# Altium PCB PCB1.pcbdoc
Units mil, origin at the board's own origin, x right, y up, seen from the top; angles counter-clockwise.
Board outline 2240 x 2165 mil, 2 copper layers (Top Layer, Bottom Layer); 16 components, 27 nets, 73 pads, 23 vias.
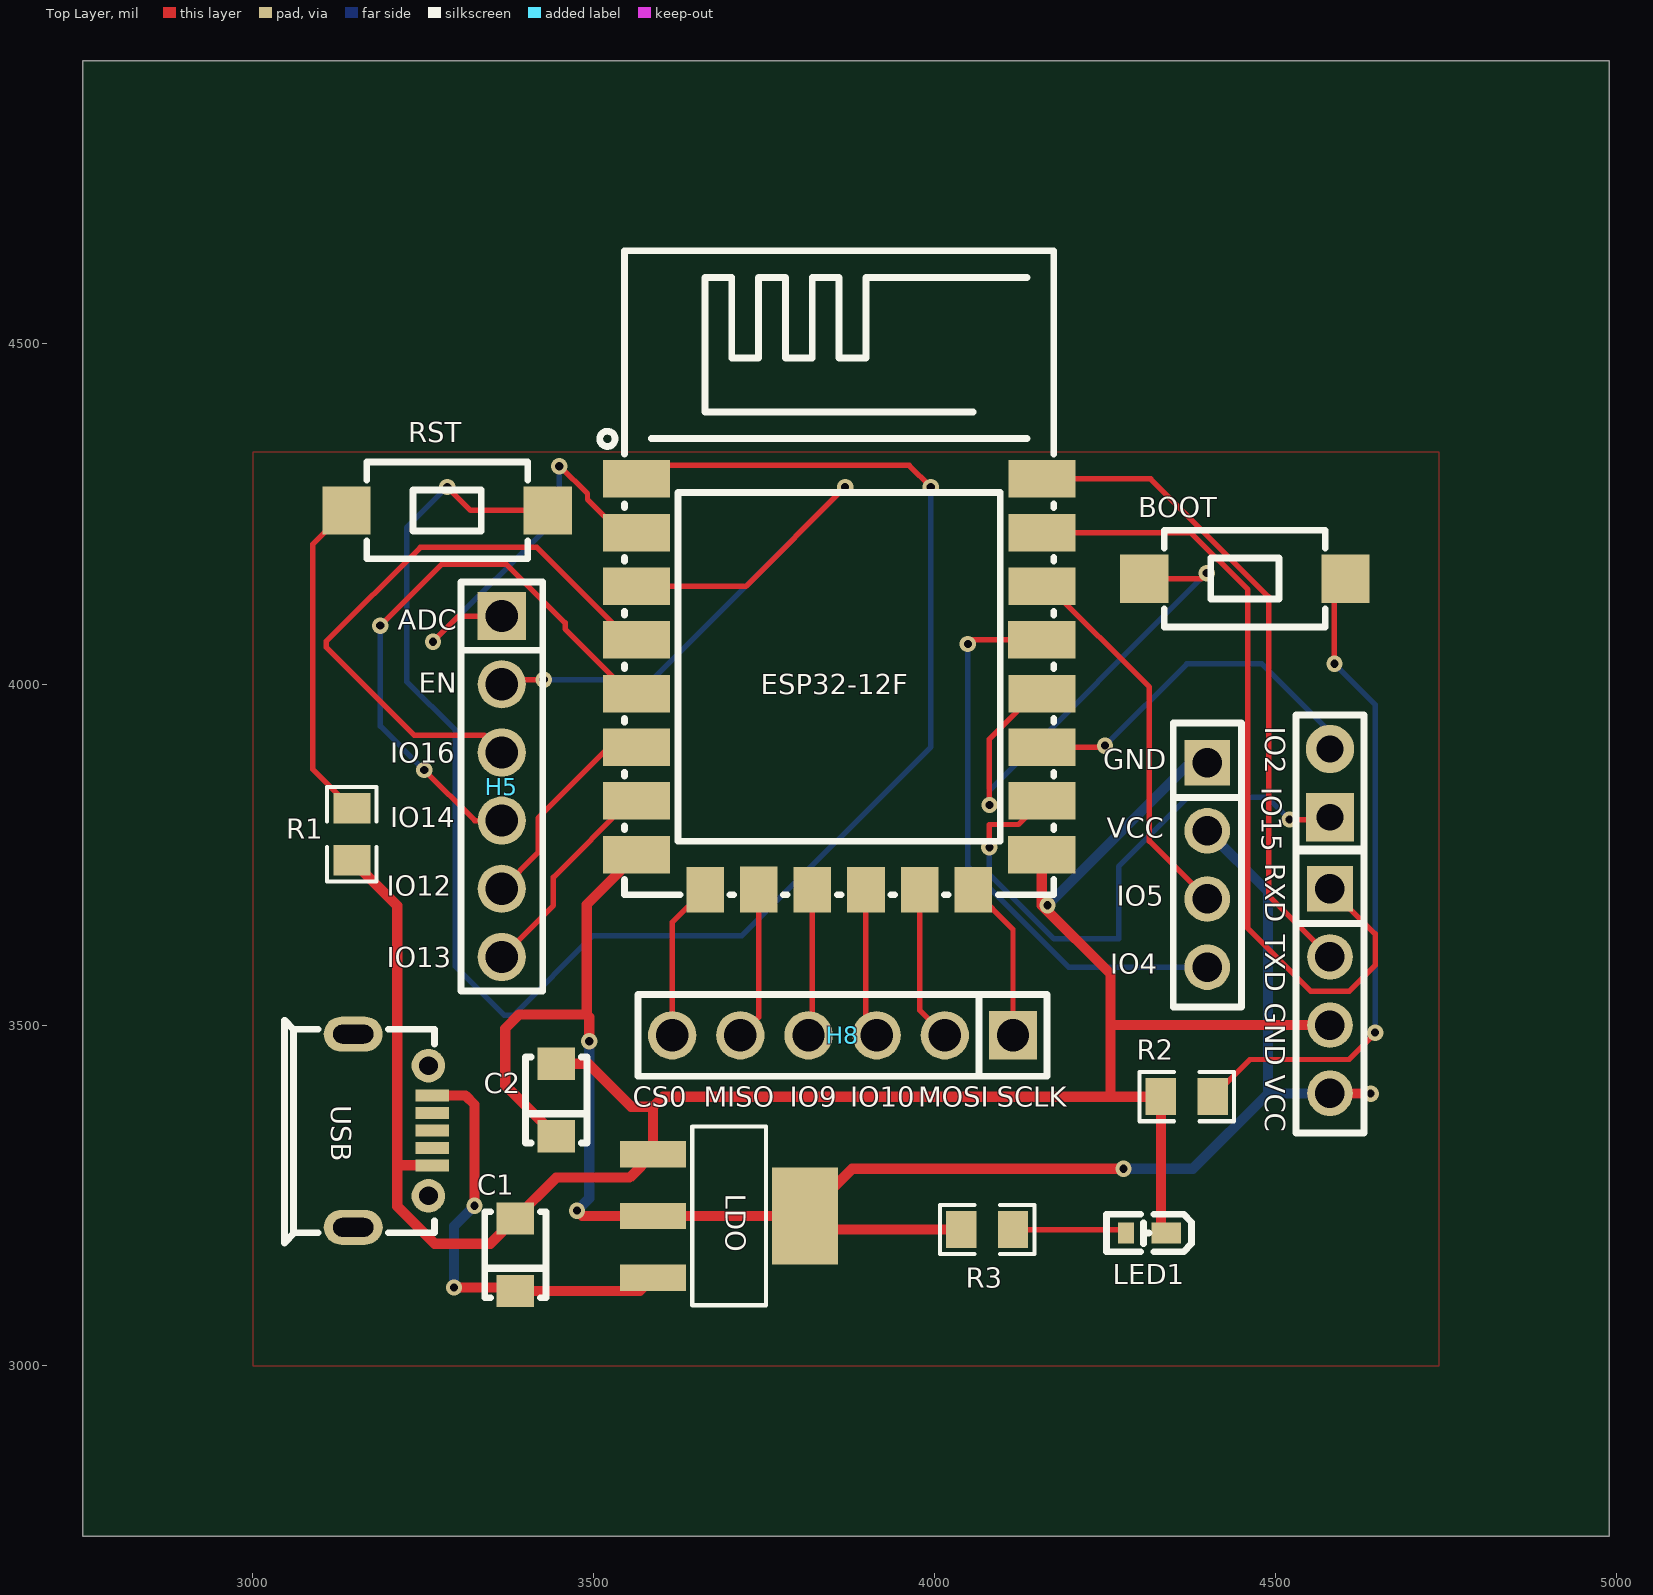
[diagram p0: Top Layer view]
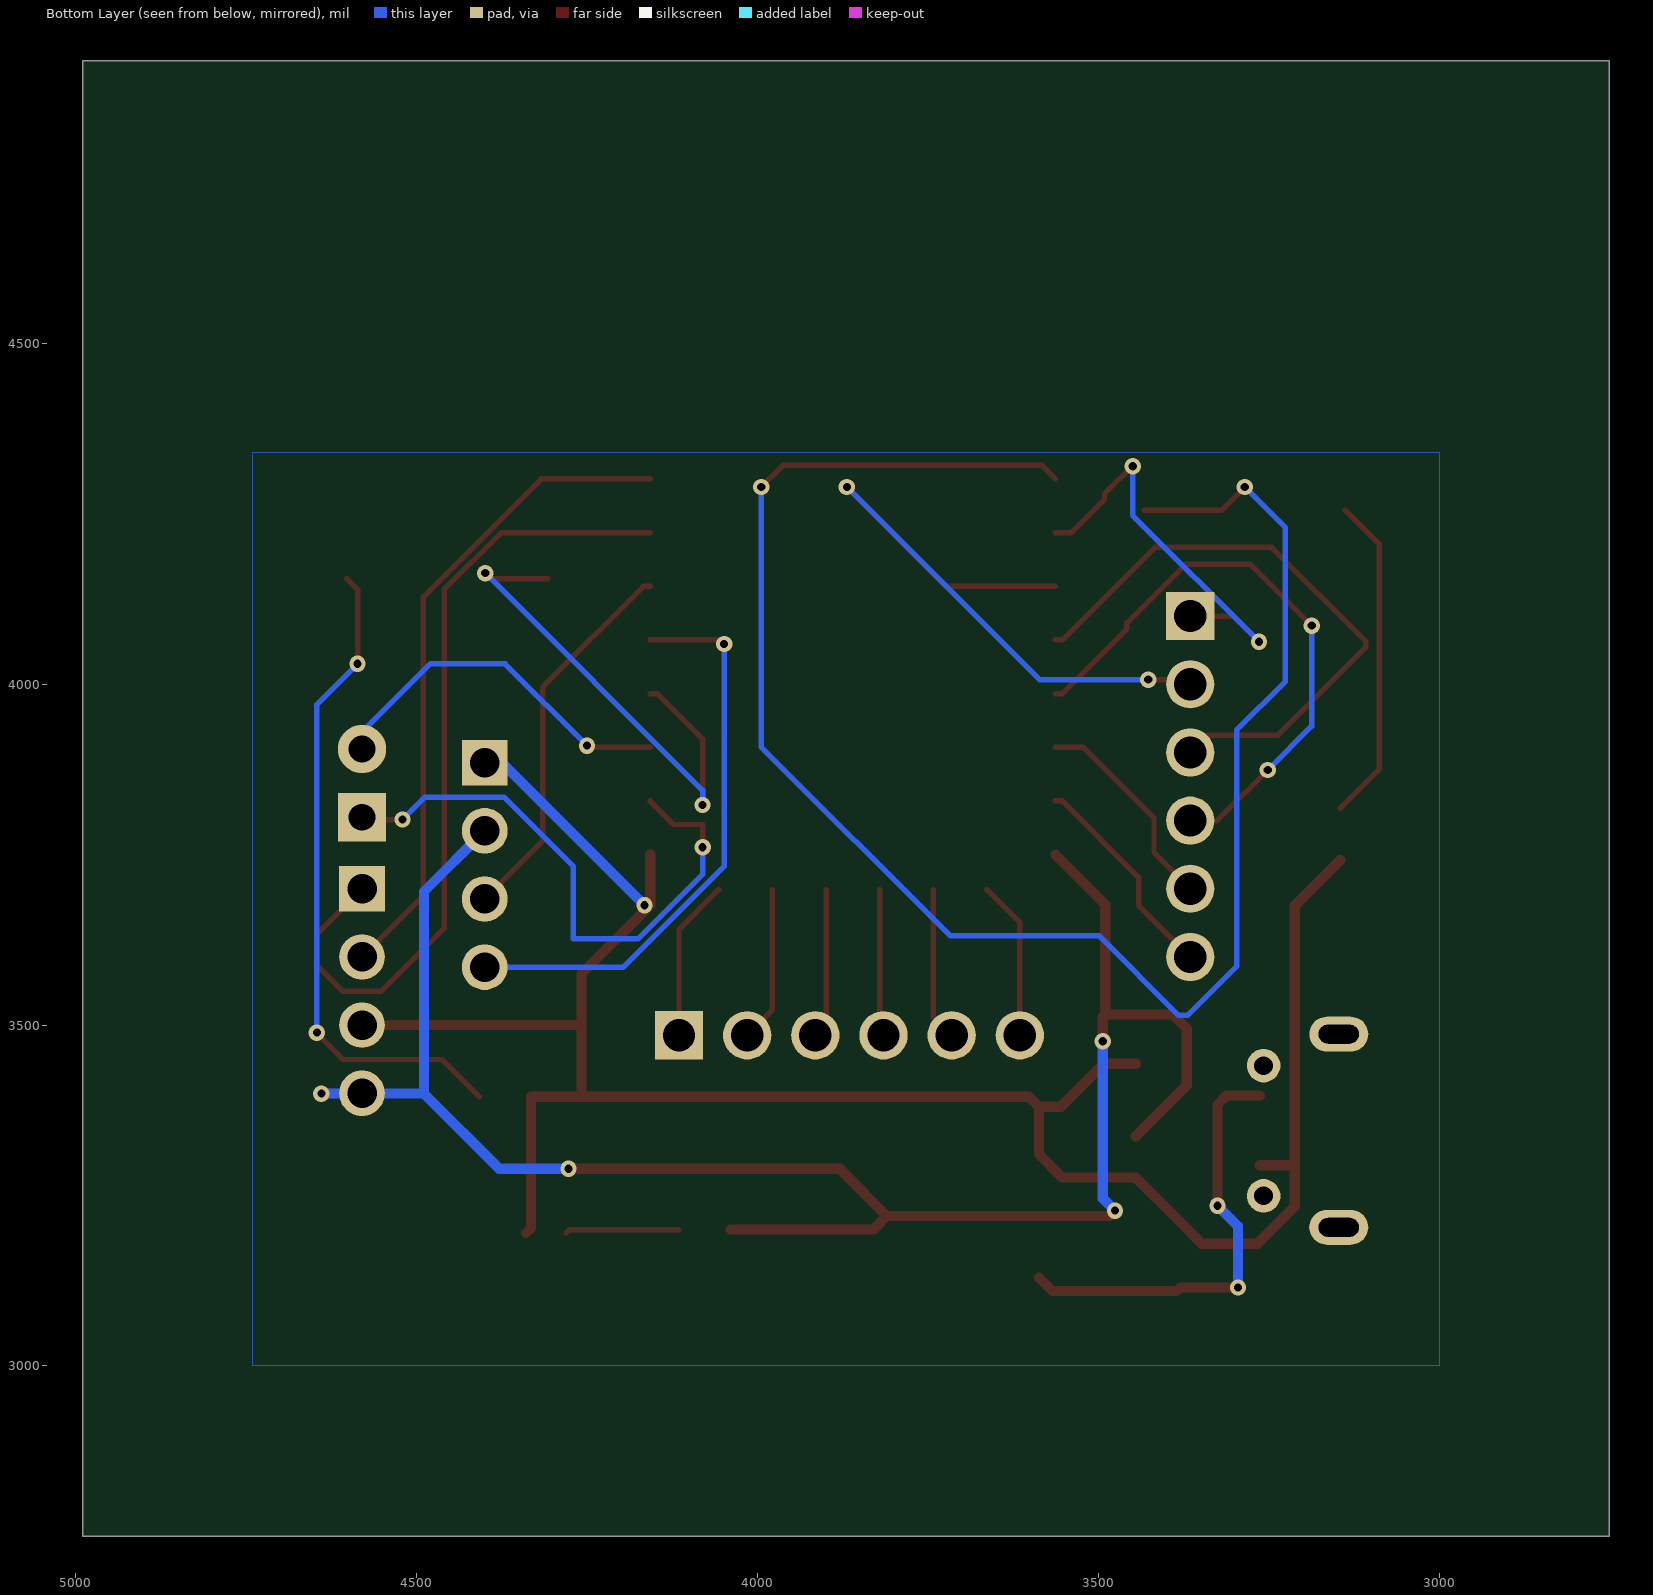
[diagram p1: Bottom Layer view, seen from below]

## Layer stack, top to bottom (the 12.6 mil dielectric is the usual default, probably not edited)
Top Solder: solder mask 0.4, Solder Resist, Dk 3.5
Top Layer: signal copper 1.4
Dielectric 1: dielectric 12.6, FR-4, Dk 4.8
Bottom Layer: signal copper 1.4
Bottom Solder: solder mask 0.4, Solder Resist, Dk 3.5

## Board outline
4990,2750 2750,2750 2750,4915 4990,4915

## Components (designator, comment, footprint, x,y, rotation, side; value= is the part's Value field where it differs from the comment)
BOOT "TC-3602-4.3-260G" 292f29fadf1e48b7a3b4ebaa9ab8793d 4455,4155 r0 top
C1 "CA45-A-16V-22uF-K" cef38e23011846a78147c20d2fc68810 3385,3163.1 r90 top
C2 "CA45-A-16V-22uF-K" cef38e23011846a78147c20d2fc68810 3445,3390 r90 top
ESP32-12F "ESP-12F(ESP8266MOD)" 6cb623ee6e8a4130b9d8b69253f68ddd 3860,4000 r270 top
H5 "Z-211-0611-0021-001" 89763fb670774c40826e2f4c92c8dd55 3365,3850 r270 top
H8 "Z-211-0611-0021-001" 89763fb670774c40826e2f4c92c8dd55 3865,3485 r180 top
IO2 "B-2100S02P-A110" aca87a76b5964f00b5eec5a18ff8502a 4580,3855 r90 top
IO15 "B-2100S04P-A110" c08b39ca13c142208e0ab31493f07b48 4400,3735 r270 top
LDO "AMS1117-2.5" 89b6391cbf9345aca1f6cf9b3f709359 3698.39,3220 r180 top
LED1 "19-213/GHC-ZN2Q1B8X/3T" LED-SMD_L1.6-W0.8-RD-2 4310,3195 r180 top
R1 "AR05DTCW1002" 005aad4e5a6043c4a1a7746d5863ed57 3145,3780 r90 top
R2 "AR05DTCW1002" 005aad4e5a6043c4a1a7746d5863ed57 4370,3395 r0 top
R3 "AR05DTCW1002" R0805 4076.96,3200 r180 top
RST "TC-3602-4.3-260G" 292f29fadf1e48b7a3b4ebaa9ab8793d 3285,4255 r180 top
RXD "B-2100S04P-A110" c08b39ca13c142208e0ab31493f07b48 4580,3550 r270 top
USB "U-F-M5DD-Y-L" c2fd68432a4d4a039f2cb9165cb8b9e0 3205,3345 r270 top

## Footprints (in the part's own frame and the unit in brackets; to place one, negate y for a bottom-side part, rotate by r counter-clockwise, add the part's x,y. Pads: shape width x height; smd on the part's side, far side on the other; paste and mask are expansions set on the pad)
005aad4e5a6043c4a1a7746d5863ed57 [mil]
  rect 44.59x54.21 smd: 1(-38.04,0) 2(38.04,0)
  silkscreen extent -69,-36 69,36
6cb623ee6e8a4130b9d8b69253f68ddd [mil]
  rect 55.1x98.4 smd: 1(-301.2,-297.3) 2(-222.5,-297.3) 3(-143.7,-297.3) 4(-65,-297.3) 5(13.8,-297.3) 6(92.5,-297.3) 7(171.2,-297.3) 8(250,-297.3) 9(250,297.2) 10(171.2,297.3) 11(92.5,297.3) 12(13.8,297.3) 13(-65,297.2) 14(-143.7,297.3) 15(-222.5,297.3) 16(-301.2,297.3)
  rect 66.9x55.1 smd: 17(301.2,-196.8) 18(301.1,-118.2) 19(301.2,-39.5) 20(301.2,39.3) 21(301.2,118) 22(301.2,196.7)
  silkscreen extent -636,-351 309,315
89b6391cbf9345aca1f6cf9b3f709359 [mm]
  rect 2.47x0.98 smd: 1(2.835,-2.3) 2(2.835,0) 3(2.835,2.3)
  rect 2.47x3.6 smd: 4(-2.835,0)
  silkscreen extent -1.37,-3.33 1.37,3.33
292f29fadf1e48b7a3b4ebaa9ab8793d [mm]
  rect 1.8x1.8 smd: 1(-3.75,0) 2(3.75,0)
  silkscreen extent -3,-1.8 3,1.8
89763fb670774c40826e2f4c92c8dd55 [mm]
  rect 1.8x1.8 hole 1.2: 1(-6.35,0)
  round 1.8 hole 1.2: 2(-3.81,0) 3(-1.27,0) 4(1.27,0) 5(3.81,0) 6(6.35,0)
  silkscreen extent -7.62,-1.52 7.62,1.52
aca87a76b5964f00b5eec5a18ff8502a [mm]
  rect 1.8x1.8 hole 1: 1(-1.27,0)
  round 1.8 hole 1: 2(1.27,0)
  silkscreen extent -2.54,-1.27 2.54,1.27
c2fd68432a4d4a039f2cb9165cb8b9e0 [mm]
  oval 1.3x2.2 hole 0.7 slot 1.5 at 90 deg: 0(-3.6,-1.471) 0(3.6,-1.47)
  round 1.25 hole 0.7: 0(-2.425,1.329) 0(2.425,1.329)
  rect 0.45x1.25 smd: 1(-1.31,1.471) 2(-0.66,1.471) 3(-0.01,1.471) 4(0.64,1.471) 5(1.29,1.471)
  silkscreen extent -4.12,-4.03 4.18,1.56
c08b39ca13c142208e0ab31493f07b48 [mil]
  rect 66.9x66.9 hole 43.3: 1(-150,0)
  round 66.9 hole 43.3: 2(-50,0) 3(50,0) 4(150,0)
  silkscreen extent -208,-50 208,50
cef38e23011846a78147c20d2fc68810 [mil]
  rect 47.2x55.1 smd: 1(-53.1,0) 2(53.2,0)
  silkscreen extent -63,-45 63,45
LED-SMD_L1.6-W0.8-RD-2 [mm]
  rect 0.6x0.8 smd: 1(0.75,0)
  rect 1.1x0.8 smd: 2(-0.75,0)
  silkscreen extent -1.7,-0.7 1.47,0.7
R0805 [mil]
  rect 44.59x54.21 smd: 1(-38.04,0) 2(38.04,0)
  silkscreen extent -69,-36 69,36

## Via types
v1: diameter 24.02, hole 12.01, Top Layer to Bottom Layer, 23 vias

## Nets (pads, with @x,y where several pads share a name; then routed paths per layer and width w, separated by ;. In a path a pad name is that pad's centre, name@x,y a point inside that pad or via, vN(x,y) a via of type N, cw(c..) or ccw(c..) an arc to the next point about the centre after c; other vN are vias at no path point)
$1N2156: BOOT.2 | length 975.3
  Top Layer w8: 4408.04,3395 4462.55,3449.51 4608.17,3449.51 4646.2,3487.55 v1(4646.2,3489) ; v1(4586.54,4030) 4586.54,4138.9 BOOT.2
  Bottom Layer w8: v1(4586.54,4030) 4646.2,3970.34 v1(4646.2,3489)
$1N2895: RST.2 | length 481.4
  Top Layer w8: RST.2 3087.55,4205.19 3087.55,3875.49 3145,3818.04
$1N6353: LED1.1 R3.1 | length 167.5
  Top Layer w8: R3.1 4275.47,3200 LED1.1
+5V: LDO.3 USB.1 | length 650.4
  Top Layer w15: USB.1 3311.99,3396.59 3325,3383.58 v1(3325,3235) ; v1(3295,3115) 3380,3115 3385,3110 3567.33,3110 LDO.3
  Bottom Layer w15: v1(3295,3115) 3295,3205 v1(3325,3235)
ADC: ESP32-12F.2 | length 609.1
  Top Layer w8: v1(3264.21,4062.44) 3301.76,4100 3365,4100 ; v1(3449.35,4319.82) 3450.69,4319.82 3490.79,4279.72 3490.79,4271.16 3539.44,4222.5 ESP32-12F.2
  Bottom Layer w8: v1(3264.21,4062.44) 3449.35,4247.59 v1(3449.35,4319.82)
CS0: ESP32-12F.17 H8.6 | length 233.8
  Top Layer w8: H8.6 3615,3650.6 ESP32-12F.17
EN: ESP32-12F.3 H5.2 | length 990
  Top Layer w8: H5.2 3371.78,4006.78 v1(3426.69,4006.78) ; ESP32-12F.3 3722.99,4143.7 v1(3868.71,4289.42)
  Bottom Layer w8: v1(3426.69,4006.78) 3586.08,4006.78 v1(3868.71,4289.42)
GND: C1.2 C2.2 ESP32-12F.9 R1.1 R2.1 RXD.3 USB.5 | length 3278.9
  Top Layer w15: R1.1 3211.7,3675.26 3211.7,3294.23 ; USB.5 3211.7,3294.23 ; C2.2 3491.8,3443.2 3554.73,3380.27 3586.78,3380.27 ; ESP32-12F.9 v1@4157.2,3675.88 ; v1(4165.61,3675.88) v1@4157.2,3675.88 ; 4339.53,3195 4331.96,3202.57 R2.1 4258.18,3395 ; RXD.3 4258.18,3500 ; 3211.7,3294.23 3211.7,3234.2 3266.64,3179.26 3347.96,3179.26 C1.2 3445,3276.3 3552.53,3276.3 3586.78,3310.55 3586.78,3380.27 ; 3586.78,3380.27 3601.51,3395 4258.18,3395 ; v1@4157.2,3675.88 4258.18,3574.9 4258.18,3500 ; 4258.18,3395 4258.18,3500
  Bottom Layer w15: v1(4165.61,3675.88) 4374.72,3885 4400,3885
GPIO0: ESP32-12F.12 | length 768.2
  Top Layer w8: v1(4080.43,3822.95) 4080.43,3919.38 4147.25,3986.2 ESP32-12F.12 ; 4307.36,4155 4391.13,4155 v1(4399.17,4163.03)
  Bottom Layer w8: v1(4080.43,3822.95) 4080.43,3844.29 v1(4399.17,4163.03)
GPIO2: ESP32-12F.11 | length 534.9
  Top Layer w8: ESP32-12F.11 4242.5,3907.5 v1@4245,3910
  Bottom Layer w8: v1(4250,3910) 4370,4030 4480,4030 4580,3930 4580,3905
GPIO4: ESP32-12F.13 IO15.4 | length 849.7
  Top Layer w8: v1(4048.75,4059.15) 4054.6,4065 ESP32-12F.13
  Bottom Layer w8: v1(4048.75,4059.15) 4048.75,3732.85 4196.6,3585 IO15.4
GPIO5: ESP32-12F.14 IO15.3 | length 565.1
  Top Layer w8: ESP32-12F.14 4167.25,4143.7 4315,3995.95 4315,3770 IO15.3
GPIO9: ESP32-12F.19 H8.4 | length 216.1
  Top Layer w8: H8.4 3820.5,3490.5 ESP32-12F.19
GPIO10: ESP32-12F.20 H8.3 | length 220.3
  Top Layer w8: ESP32-12F.20 3899.3,3500.7 H8.3
GPIO12: ESP32-12F.6 H5.5 | length 313.3
  Top Layer w8: H5.5 3418.17,3753.17 3418.17,3803.75 3521.92,3907.5 ESP32-12F.6
GPIO13: ESP32-12F.7 H5.6 | length 316.5
  Top Layer w8: H5.6 3440.8,3675.8 3440.8,3716.85 3552.75,3828.8 ESP32-12F.7
GPIO14: ESP32-12F.5 H5.4 | length 880.3
  Top Layer w8: v1(3186.84,4086.07) 3277.09,4176.32 3371.55,4176.32 3457.84,4090.03 3457.84,4081.11 3552.75,3986.2 ESP32-12F.5 ; v1(3251.28,3874.16) 3325.44,3800 H5.4
  Bottom Layer w8: v1(3186.84,4086.07) 3186.84,3938.6 v1(3251.28,3874.16)
GPIO15: ESP32-12F.10 IO2.1 | length 866.7
  Top Layer w8: v1(4080.38,3760.9) 4080.38,3794.25 4122.75,3794.25 ESP32-12F.10 ; v1(4520.54,3801.51) 4576.51,3801.51 IO2.1
  Bottom Layer w8: v1(4080.38,3760.9) 4080.38,3721.22 4175.16,3626.44 4269.95,3626.44 4269.95,3732.63 4371.83,3834.51 4487.53,3834.51 v1(4520.54,3801.51)
GPIO16: ESP32-12F.4 H5.3 | length 898.4
  Top Layer w8: H5.3 3339.63,3925.37 3236.41,3925.37 3107.82,4053.96 3107.82,4063.15 3245.6,4200.93 3416.72,4200.93 3552.65,4065 ESP32-12F.4
MISO: ESP32-12F.18 H8.5 | length 225
  Top Layer w8: H8.5 3741.8,3511.8 ESP32-12F.18
MOSI: ESP32-12F.21 H8.2 | length 229.1
  Top Layer w8: ESP32-12F.21 3978,3522 H8.2
RST: ESP32-12F.1 | length 2644.1
  Top Layer w8: v1(3285,4289.42) 3319.42,4255 3432.64,4255 ; ESP32-12F.1 3582.59,4321.09 3962.74,4321.09 v1(3994.41,4289.42)
  Bottom Layer w8: v1(3285,4289.42) 3225.52,4229.93 3225.52,4003.97 3296.87,3932.62 3296.87,3586.15 3368.7,3514.32 3382.05,3514.32 3498.9,3631.17 3717.44,3631.17 3994.41,3908.13 v1(3994.41,4289.42)
RXD: ESP32-12F.15 | length 1214.4
  Top Layer w8: ESP32-12F.15 4375.72,4222.5 4459.54,4138.67 4459.54,3641.8 4551.83,3549.51 4608.17,3549.51 4646.2,3587.55 4646.2,3633.8 4580,3700
SCLK: ESP32-12F.22 | length 237.9
  Top Layer w8: ESP32-12F.22 4115,3640.5 4115,3485
TXD: RXD.2 | length 969.8
  Top Layer w8: 4157.3,4301.2 4317.02,4301.2 4489.88,4128.34 4489.88,3690.12 RXD.2
VCC: ESP32-12F.8 IO15.2 LDO.2 LDO.4 RXD.4 | length 2840.2
  Top Layer w15: 3445,3336.9 3370,3411.9 3370,3495 3390.68,3515.68 3489.56,3515.68 ; v1(3475.35,3227.78) 3483.13,3220 LDO.2 LDO.4 ; v1(3493.41,3476.17) 3493.41,3511.82 3489.56,3515.68 ; ESP32-12F.8 3489.56,3676.86 3489.56,3515.68 ; 4038.92,3200 3830,3200 LDO.4 ; v1(4277.05,3289.32) 3879.32,3289.32 LDO.4 ; RXD.4 4580.49,3399.51 v1(4639.67,3399.51)
  Bottom Layer w15: v1(3475.35,3227.78) 3493.41,3245.84 v1(3493.41,3476.17) ; v1(4277.05,3289.32) 4378.82,3289.32 4489.01,3399.51 ; IO15.2 4489.01,3695.99 4489.01,3399.51 ; v1(4639.67,3399.51) 4489.01,3399.51
"": 
pads on no net: BOOT.1 C1.1 C2.1 ESP32-12F.16 H5.1 H8.1 IO2.2 IO15.1 LDO.1 LED1.2 R1.2 R2.2 R3.2 RST.1 RXD.1 USB.0 USB.2 USB.3 USB.4

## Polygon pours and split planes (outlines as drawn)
GND on Top Layer (solid, remove dead copper): 3000,3000 4740,3000 4740,4340 3000,4340
GND on Bottom Layer (solid, remove dead copper, pour order 1): 3000,3000 4740,3000 4740,4340 3000,4340

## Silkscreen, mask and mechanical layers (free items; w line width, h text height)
Top Overlay:
  text "ADC" at 3212.51,4079.99 h29.2
  text "EN" at 3243.29,3987.49 h29.2
  text "IO16" at 3201.22,3884.99 h29.2
  text "GND" at 4247.51,3874.99 h29.2
  text "IO14" at 3201.22,3789.99 h29.2
  text "VCC" at 4252.51,3774.99 h29.2
  text "IO12" at 3196.22,3689.99 h29.2
  text "IO5" at 4267.51,3674.99 h29.2
  text "TXD" at 4484.99,3632.49 h29.2 r270
  text "IO13" at 3196.22,3584.99 h29.2
  text "IO4" at 4257.51,3574.99 h29.2
  text "GND" at 4484.99,3532.49 h29.2 r270
  text "VCC" at 4484.99,3427.49 h29.2 r270
  text "CS0" at 3557.51,3379.99 h29.2
  text "MISO" at 3661.22,3379.99 h29.2
  text "IO9" at 3787.51,3379.99 h29.2
  text "IO10" at 3876.22,3379.99 h29.2
  text "MOSI" at 3976.22,3379.99 h29.2
  text "SCLK" at 4091.22,3379.99 h29.2
Mechanical 1:
  lines w10: 3035,3035 4685,3035 4685,4665 3035,4665 3035,3035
